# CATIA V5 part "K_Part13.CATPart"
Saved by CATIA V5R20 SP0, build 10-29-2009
Part number: Verin
Bounding box of the stored display mesh (mm): x 6.5 to 12.5, y 9.918 to 167.361, z -5.345 to 16.425
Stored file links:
  G:\Khaled_CFAO_2011\SIL\SIL_GR1\mneves\Khaled\CAD_CATIA_Modifie\K_Part13.CATPart
  G:\Khaled_CFAO_2011\SIL\SIL_GR1\mneves\Khaled\CAD_CATIA_Modifie\K_AssPince_A_Bois.CATProduct
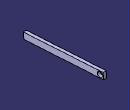
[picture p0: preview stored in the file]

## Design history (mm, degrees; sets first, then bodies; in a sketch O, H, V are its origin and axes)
External parameters (linked from other documents)
  External.Distance_Inter_Pivot = 200 mm
  `External.Epaisseur_Vérin` = 6 mm
Set1
  Plane1: linked copy from another document
  Point1: linked copy from another document
  Line1: linked copy from another document
Body1 (main body)
  Sketch1 on Plane1, origin (9.5, 0, 0), H (0, 1, 0), V (0, 0, 1)
    line L1 (9.9178, 6.6316) -> (166.6121, 16.425)
    line L2 (166.6121, 16.425) -> (167.3606, 4.4483)
    line L3 (167.3606, 4.4483) -> (10.6664, -5.3451)
    line L4 (10.6664, -5.3451) -> (9.9178, 6.6316)
    circle A1 centre (160, 10) radius 5
    point P5 (160, 10)
    reference projected point E1 (160, 10) from Point1
    reference projected line E2 (10.2921, 0.6433) -> (160, 10) from Line1
    reference projected line E3 (10.2921, 0.6433) -> (160, 10) from Line1
    reference projected point E4 (160, 10) from Point1
    reference projected line E5 (10.2921, 0.6433) -> (160, 10) from Line1
    reference projected line E6 (10.2921, 0.6433) -> (160, 10) from Line1
    radius A1 = 5 {= External.Distance_Inter_Pivot /40}
    distance E4 L2 = 7 {= External.Distance_Inter_Pivot /40+External.Distance_Inter_Pivot /100}
    distance E5 L1 = 6 {= External.Distance_Inter_Pivot /40+External.Distance_Inter_Pivot /200}
    distance E6 L3 = 6 {= External.Distance_Inter_Pivot /200+External.Distance_Inter_Pivot /40}
    distance L2 L4 = 157 {= External.Distance_Inter_Pivot *(3/4)+External.Distance_Inter_Pivot /40+External.Distance_Inter_Pivot /100}
    coincidence: P5 E1
    parallelism: E2 L1, L3 E3
    perpendicularity: L1 L2, L3 L4
  Pad1: profile Sketch1, direction (1, 0, 0), length 3 {= `External.Epaisseur_Vérin` /2}, mirrored extent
